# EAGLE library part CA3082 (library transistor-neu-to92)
TRANSISTOR ARRAY general purpose, high current common collector
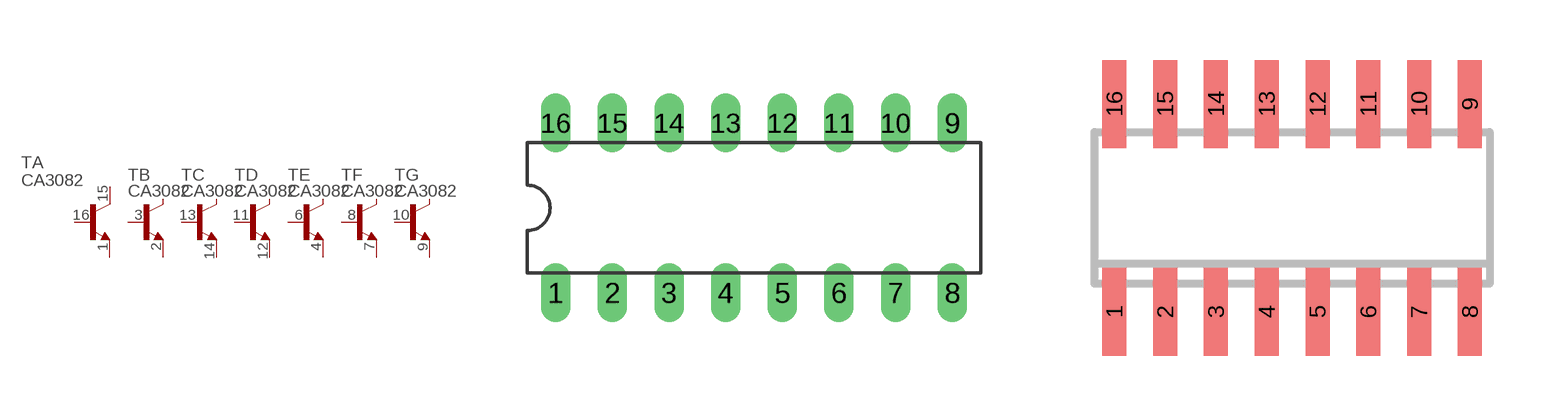
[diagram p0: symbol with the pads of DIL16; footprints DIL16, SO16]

Designator prefix T; gates B=NPN-E C=NPN-E D=NPN-E E=NPN-E F=NPN-E G=NPN-E A=NPN-PAD

## CA3082  [DIL16]
1  A:E  pas
2  B:E  pas
3  B:B  pas
4  E:E  pas
6  E:B  pas
7  F:E  pas
8  F:B  pas
9  G:E  pas
10  G:B  pas
11  D:B  pas
12  D:E  pas
13  C:B  pas
14  C:E  pas
15  A:C  pas
16  A:B  pas

## CA3082M  [SO16]
Pads as for DIL16

## Footprint DIL16 (pad centres in mm)
Dual In Line Package
drill 0.813 long: 1 -8.89,-3.81; 2 -6.35,-3.81; 3 -3.81,-3.81; 4 -1.27,-3.81; 5 1.27,-3.81; 6 3.81,-3.81; 7 6.35,-3.81; 8 8.89,-3.81; 9 8.89,3.81; 10 6.35,3.81; 11 3.81,3.81; 12 1.27,3.81; 13 -1.27,3.81; 14 -3.81,3.81; 15 -6.35,3.81; 16 -8.89,3.81

## Footprint SO16 (pad centres in mm)
SMALL OUTLINE INTEGRATED CIRCUIT body 3.9 mm/JEDEC MS-012AC
smd 0.6 x 2.2: 1 -4.445,-2.6; 2 -3.175,-2.6; 3 -1.905,-2.6; 4 -0.635,-2.6; 5 0.635,-2.6; 6 1.905,-2.6; 7 3.175,-2.6; 8 4.445,-2.6; 9 4.445,2.6; 10 3.175,2.6; 11 1.905,2.6; 12 0.635,2.6; 13 -0.635,2.6; 14 -1.905,2.6; 15 -3.175,2.6; 16 -4.445,2.6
